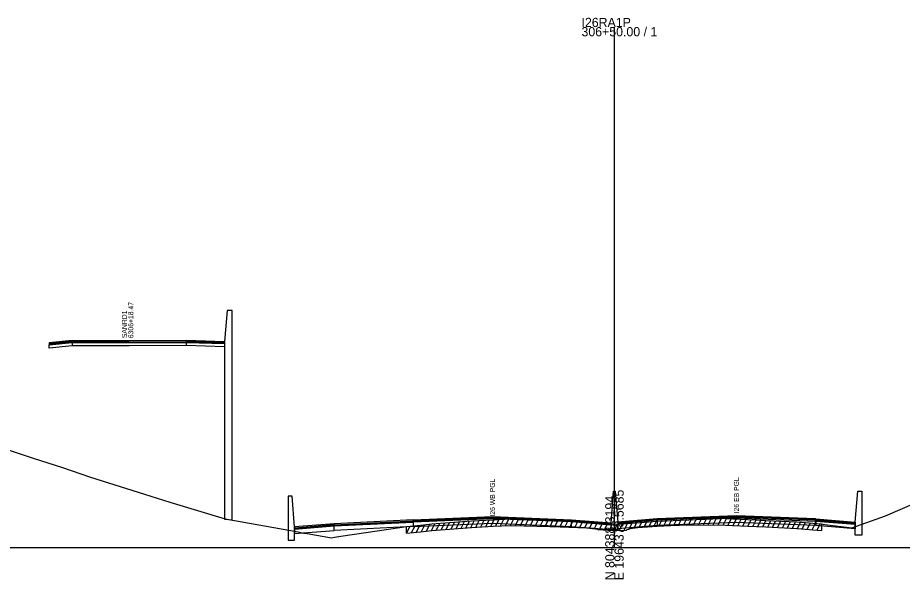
# Model space of a CAD drawing. Extents: x 1017 to 19997, y -1947 to 50737.
# Drawn here: x 12419 to 12687.3, y 6490.3 to 6660.6 of the extents above; entities that cross this region are included whole.
import ezdxf

# ---------------------------------------------------------------- set-up
doc = ezdxf.new("R2010")
doc.units = 0
for name, color, linetype in [('RD_GPK_XS_Cell', 7, 'Continuous'), ('RD_XS_Base', 7, 'Continuous'), ('RD_XS_ExGround', 7, 'Continuous'), ('RD_XS_ExPaveRet', 7, 'Continuous'), ('RD_XS_MedBWall', 7, 'Continuous'), ('RD_XS_Pave', 7, 'Continuous'), ('RD_XS_PaveOvlay', 7, 'Continuous'), ('RD_XS_TX_Notes', 7, 'Continuous')]:
    doc.layers.add(name, color=color, linetype=linetype)

msp = doc.modelspace()

# ---------------------------------------------------------------- linework, layer by layer
at = {"layer": 'RD_GPK_XS_Cell'}
for p, q in [((12600, 6500), (12600, 6657.75)), ((12000, 6500), (12600, 6500)), ((12600, 6500), (13200, 6500))]:
    msp.add_line(p, q, dxfattribs=at)
at = {"layer": 'RD_XS_Base'}
for points in [[(12428.6, 6561.38), (12435.53, 6562.12)], [(12428.6, 6560.38), (12428.6, 6561.38)], [(12435.53, 6561.12), (12428.6, 6560.38)], [(12435.53, 6562.12), (12452.85, 6562.12), (12470.18, 6562.15)], [(12435.53, 6562.12), (12435.53, 6561.12)], [(12470.18, 6561.15), (12452.85, 6561.12), (12435.53, 6561.12)], [(12470.18, 6562.15), (12481.73, 6561.79)], [(12470.18, 6561.15), (12470.18, 6562.15)], [(12481.73, 6560.79), (12470.18, 6561.15)], [(12481.73, 6561.79), (12481.73, 6560.79)], [(12587, 6507.69), (12563, 6508.65), (12539, 6507.68)], [(12613, 6507.95), (12637, 6508.91), (12661, 6507.95)], [(12515, 6506.48), (12503, 6505.52)], [(12515, 6506.48), (12539, 6507.68)], [(12515, 6505.14), (12515, 6506.48)], [(12539, 6506.34), (12515, 6505.14)], [(12539, 6507.68), (12539, 6506.34)], [(12539, 6506.34), (12563, 6507.31), (12587, 6506.35)], [(12587, 6506.35), (12587, 6507.69)], [(12599, 6506.75), (12587, 6507.69)], [(12587, 6506.35), (12599, 6505.41)], [(12599, 6505.41), (12599, 6506.75)], [(12601, 6507), (12613, 6507.95)], [(12601, 6505.66), (12601, 6507)], [(12613, 6506.61), (12601, 6505.66)], [(12613, 6507.95), (12613, 6506.61)], [(12661, 6506.61), (12637, 6507.57), (12613, 6506.61)], [(12661, 6507.95), (12661.05, 6507.94)], [(12661, 6506.61), (12661, 6507.95)], [(12661.05, 6506.6), (12661, 6506.61)], [(12661.05, 6507.94), (12673.05, 6506.98)], [(12661.05, 6506.6), (12661.05, 6507.94)], [(12661.05, 6507.94), (12661.05, 6506.6)], [(12673.05, 6505.64), (12661.05, 6506.6)], [(12673.05, 6506.98), (12673.05, 6505.64)], [(12503, 6505.52), (12503, 6504.18)], [(12503, 6504.18), (12515, 6505.14)]]:
    msp.add_lwpolyline(points, dxfattribs=at)
at = {"layer": 'RD_XS_ExGround'}
msp.add_lwpolyline([(12408.26, 6532.18), (12423.66, 6527.03), (12432.56, 6524.17), (12441.14, 6521.29), (12457.45, 6516.14), (12465.18, 6513.73), (12481.9, 6508.65), (12504.08, 6504.68), (12505.76, 6504.34), (12506.76, 6504.19), (12514.21, 6502.93), (12515.05, 6503.04), (12517.04, 6503.35), (12532.18, 6505.6), (12536.97, 6506.32), (12541.13, 6506.72), (12544.64, 6507.09), (12550.02, 6507.51), (12556.67, 6508.02), (12563.18, 6508.37), (12568.58, 6508.66), (12580.45, 6508.33), (12580.79, 6508.32), (12591.49, 6507.89), (12594.24, 6507.65), (12594.71, 6507.61), (12595.08, 6507.45), (12598.01, 6507.18), (12600, 6507.1), (12600.71, 6507.07), (12603.64, 6507.25), (12603.9, 6507.43), (12604.4, 6507.48), (12604.67, 6507.68), (12607.08, 6508.01), (12612.99, 6508.38), (12619.12, 6508.76), (12619.75, 6508.77), (12631.32, 6508.84), (12640.5, 6508.42), (12643.1, 6508.31), (12645.92, 6508.18), (12655.27, 6507.75), (12656.77, 6507.62), (12660.12, 6507.34), (12662.8, 6507.14), (12663.85, 6506.96), (12672.04, 6505.92), (12682.25, 6509.52), (12691.05, 6513.37)], dxfattribs=at)
at = {"layer": 'RD_XS_ExPaveRet'}
for p, q in [((12566.97, 6506.57), (12567.99, 6508.63)), ((12568.47, 6506.65), (12569.46, 6508.63)), ((12616.47, 6506.6), (12617.5, 6508.66)), ((12617.97, 6506.69), (12619, 6508.76)), ((12619.47, 6506.76), (12620.47, 6508.77)), ((12620.97, 6506.77), (12621.97, 6508.78)), ((12622.47, 6506.78), (12623.47, 6508.79)), ((12623.97, 6506.79), (12624.97, 6508.8)), ((12625.47, 6506.8), (12626.47, 6508.81)), ((12626.97, 6506.81), (12627.97, 6508.81)), ((12628.47, 6506.82), (12629.47, 6508.82)), ((12629.97, 6506.83), (12630.97, 6508.83)), ((12631.47, 6506.83), (12632.44, 6508.78)), ((12632.97, 6506.76), (12633.94, 6508.72)), ((12634.47, 6506.69), (12635.44, 6508.65)), ((12536.97, 6504.32), (12538.02, 6506.42)), ((12536.97, 6504.32), (12536.97, 6506.32)), ((12538.47, 6504.47), (12539.52, 6506.57)), ((12539.97, 6504.61), (12541.02, 6506.71)), ((12541.47, 6504.76), (12542.52, 6506.87)), ((12542.97, 6504.91), (12544.02, 6507.02)), ((12544.47, 6505.07), (12545.51, 6507.16)), ((12545.97, 6505.19), (12547.01, 6507.27)), ((12547.47, 6505.31), (12548.51, 6507.39)), ((12548.97, 6505.43), (12550.01, 6507.51)), ((12550.02, 6505.51), (12556.67, 6506.02)), ((12550.47, 6505.54), (12551.51, 6507.62)), ((12551.97, 6505.66), (12553.01, 6507.74)), ((12553.47, 6505.77), (12554.51, 6507.85)), ((12554.97, 6505.89), (12556.01, 6507.97)), ((12556.47, 6506), (12557.5, 6508.06)), ((12556.67, 6506.02), (12563.18, 6506.37)), ((12557.97, 6506.09), (12558.99, 6508.14)), ((12559.47, 6506.17), (12560.49, 6508.22)), ((12560.97, 6506.25), (12561.99, 6508.3)), ((12562.47, 6506.33), (12563.49, 6508.39)), ((12563.18, 6506.37), (12568.58, 6506.66)), ((12563.97, 6506.41), (12564.99, 6508.47)), ((12565.47, 6506.49), (12566.49, 6508.55)), ((12568.58, 6506.66), (12580.45, 6506.33)), ((12569.97, 6506.62), (12570.95, 6508.59)), ((12571.47, 6506.58), (12572.45, 6508.55)), ((12572.97, 6506.54), (12573.95, 6508.51)), ((12574.47, 6506.5), (12575.45, 6508.47)), ((12575.97, 6506.45), (12576.95, 6508.43)), ((12577.47, 6506.41), (12578.45, 6508.39)), ((12578.97, 6506.37), (12579.95, 6508.35)), ((12580.45, 6506.33), (12580.79, 6506.32)), ((12580.47, 6506.33), (12581.45, 6508.29)), ((12580.79, 6506.32), (12591.49, 6505.89)), ((12581.97, 6506.27), (12582.95, 6508.23)), ((12583.47, 6506.21), (12584.45, 6508.17)), ((12584.97, 6506.15), (12585.95, 6508.11)), ((12586.47, 6506.09), (12587.45, 6508.05)), ((12587.97, 6506.03), (12588.95, 6507.99)), ((12589.47, 6505.97), (12590.45, 6507.93)), ((12590.97, 6505.91), (12591.94, 6507.85)), ((12592.47, 6505.81), (12593.42, 6507.72)), ((12593.97, 6505.68), (12594.89, 6507.53)), ((12595.47, 6505.42), (12596.42, 6507.33)), ((12596.97, 6505.28), (12597.92, 6507.19)), ((12598.47, 6505.16), (12599.45, 6507.12)), ((12599.97, 6505.1), (12600.96, 6507.09)), ((12601.47, 6505.12), (12602.5, 6507.18)), ((12602.97, 6505.21), (12604.09, 6507.45)), ((12604.47, 6505.53), (12605.61, 6507.81)), ((12604.67, 6505.68), (12607.08, 6506.01)), ((12605.97, 6505.86), (12607.04, 6508)), ((12607.08, 6506.01), (12612.99, 6506.38)), ((12607.47, 6506.03), (12608.5, 6508.1)), ((12608.97, 6506.13), (12610, 6508.19)), ((12610.47, 6506.22), (12611.5, 6508.29)), ((12611.97, 6506.31), (12613, 6508.38)), ((12612.99, 6506.38), (12619.12, 6506.76)), ((12613.47, 6506.41), (12614.5, 6508.47)), ((12614.97, 6506.5), (12616, 6508.57)), ((12619.12, 6506.76), (12619.75, 6506.77)), ((12619.75, 6506.77), (12631.32, 6506.84)), ((12631.32, 6506.84), (12640.5, 6506.42)), ((12635.97, 6506.63), (12636.94, 6508.58)), ((12637.47, 6506.56), (12638.44, 6508.51)), ((12638.97, 6506.49), (12639.94, 6508.45)), ((12640.47, 6506.42), (12641.45, 6508.38)), ((12640.5, 6506.42), (12643.1, 6506.31)), ((12641.97, 6506.36), (12642.95, 6508.32)), ((12643.1, 6506.31), (12645.92, 6506.18)), ((12643.47, 6506.29), (12644.44, 6508.25)), ((12644.97, 6506.22), (12645.94, 6508.18)), ((12645.92, 6506.18), (12655.27, 6505.75)), ((12646.47, 6506.15), (12647.44, 6508.11)), ((12647.97, 6506.08), (12648.94, 6508.04)), ((12649.47, 6506.01), (12650.44, 6507.97)), ((12650.97, 6505.94), (12651.94, 6507.9)), ((12652.47, 6505.88), (12653.44, 6507.83)), ((12653.97, 6505.81), (12654.94, 6507.76)), ((12655.47, 6505.73), (12656.43, 6507.65)), ((12656.97, 6505.6), (12657.93, 6507.52)), ((12658.47, 6505.48), (12659.43, 6507.4)), ((12659.97, 6505.35), (12660.93, 6507.28)), ((12661.47, 6505.24), (12662.43, 6507.17)), ((12662.8, 6507.14), (12662.8, 6505.14)), ((12536.97, 6504.32), (12541.13, 6504.72)), ((12541.13, 6504.72), (12544.64, 6505.09)), ((12544.64, 6505.09), (12550.02, 6505.51)), ((12591.49, 6505.89), (12594.24, 6505.65)), ((12594.24, 6505.65), (12594.71, 6505.61)), ((12594.71, 6505.61), (12595.08, 6505.45)), ((12595.08, 6505.45), (12598.01, 6505.18)), ((12598.01, 6505.18), (12600, 6505.1)), ((12600, 6505.1), (12600.71, 6505.07)), ((12600.71, 6505.07), (12603.64, 6505.25)), ((12603.64, 6505.25), (12603.9, 6505.43)), ((12603.9, 6505.43), (12604.4, 6505.48)), ((12604.4, 6505.48), (12604.67, 6505.68)), ((12655.27, 6505.75), (12656.77, 6505.62)), ((12656.77, 6505.62), (12660.12, 6505.34)), ((12660.12, 6505.34), (12662.8, 6505.14))]:
    msp.add_line(p, q, dxfattribs=at)
at = {"layer": 'RD_XS_MedBWall'}
for points in [[(12484.04, 6571.85), (12482.59, 6571.8), (12481.73, 6562.42)], [(12484.04, 6508.38), (12484.04, 6571.85)], [(12481.73, 6562.42), (12481.73, 6508.55)], [(12599, 6507.4), (12599.75, 6517), (12600.25, 6517), (12601, 6507.66)], [(12673.05, 6507.66), (12673.8, 6517), (12675.05, 6517)], [(12675.05, 6517), (12675.05, 6503.66)], [(12503, 6506.2), (12502.25, 6515.54), (12501, 6515.54)], [(12501, 6515.54), (12501, 6502.2)], [(12481.73, 6508.55), (12484.04, 6508.38)], [(12503, 6502.2), (12503, 6506.2)], [(12599, 6505.4), (12599, 6507.4)], [(12601, 6507.66), (12601, 6505.4)], [(12673.05, 6503.66), (12673.05, 6507.66)], [(12601, 6505.4), (12599, 6505.4)], [(12675.05, 6503.66), (12673.05, 6503.66)], [(12501, 6502.2), (12503, 6502.2)]]:
    msp.add_lwpolyline(points, dxfattribs=at)
at = {"layer": 'RD_XS_Pave'}
for points in [[(12435.53, 6562.43), (12428.6, 6561.72)], [(12470.18, 6562.47), (12452.85, 6562.44), (12435.53, 6562.43)], [(12435.53, 6562.43), (12435.53, 6562.12)], [(12470.18, 6562.15), (12470.18, 6562.47)], [(12470.18, 6562.47), (12481.73, 6562.11)], [(12428.6, 6561.38), (12435.53, 6562.12)], [(12428.6, 6561.72), (12428.6, 6561.38)], [(12435.53, 6562.12), (12452.85, 6562.12), (12470.18, 6562.15)], [(12481.73, 6561.79), (12470.18, 6562.15)], [(12481.73, 6562.11), (12481.73, 6561.79)], [(12539, 6508.02), (12563, 6508.99), (12587, 6508.03)], [(12587, 6507.69), (12563, 6508.65), (12539, 6507.68)], [(12661, 6508.29), (12637, 6509.25), (12613, 6508.29)], [(12613, 6507.95), (12637, 6508.91), (12661, 6507.95)], [(12515, 6506.82), (12503, 6505.86)], [(12503, 6505.52), (12515, 6506.48)], [(12515, 6506.82), (12539, 6508.02)], [(12539, 6507.68), (12515, 6506.48)], [(12515, 6506.48), (12515, 6506.82)], [(12539, 6507.68), (12539, 6508.02)], [(12587, 6508.03), (12599, 6507.09)], [(12587, 6507.69), (12587, 6508.03)], [(12599, 6506.75), (12587, 6507.69)], [(12599, 6507.09), (12599, 6506.75)], [(12613, 6508.29), (12601, 6507.34)], [(12601, 6507), (12613, 6507.95)], [(12601, 6507.34), (12601, 6507)], [(12613, 6508.29), (12613, 6507.95)], [(12661, 6508.29), (12661.05, 6508.28)], [(12661, 6507.95), (12661, 6508.29)], [(12661.05, 6507.94), (12661, 6507.95)], [(12661.05, 6508.28), (12673.05, 6507.32)], [(12661.05, 6507.94), (12661.05, 6508.28)], [(12661.05, 6508.28), (12661.05, 6507.94)], [(12673.05, 6506.98), (12661.05, 6507.94)], [(12673.05, 6507.32), (12673.05, 6506.98)], [(12503, 6505.86), (12503, 6505.52)]]:
    msp.add_lwpolyline(points, dxfattribs=at)
at = {"layer": 'RD_XS_PaveOvlay'}
for points in [[(12435.53, 6562.75), (12428.6, 6562.04)], [(12428.6, 6561.72), (12435.53, 6562.43)], [(12435.53, 6562.75), (12452.85, 6562.75), (12470.18, 6562.79)], [(12435.53, 6562.43), (12435.53, 6562.75)], [(12470.18, 6562.47), (12452.85, 6562.44), (12435.53, 6562.43)], [(12470.18, 6562.79), (12470.18, 6562.47)], [(12470.18, 6562.79), (12481.73, 6562.42)], [(12481.73, 6562.11), (12470.18, 6562.47)], [(12481.73, 6562.42), (12481.73, 6562.11)], [(12428.6, 6562.04), (12428.6, 6561.72)], [(12539, 6508.36), (12563, 6509.32), (12587, 6508.36)], [(12587, 6508.03), (12563, 6508.99), (12539, 6508.02)], [(12613, 6508.62), (12601, 6507.66)], [(12661, 6508.62), (12637, 6509.58), (12613, 6508.62)], [(12613, 6508.29), (12637, 6509.25), (12661, 6508.29)], [(12613, 6508.62), (12613, 6508.29)], [(12661, 6508.29), (12661, 6508.62)], [(12661, 6508.62), (12661.05, 6508.62)], [(12661.05, 6508.62), (12673.05, 6507.66)], [(12661.05, 6508.28), (12661.05, 6508.62)], [(12661.05, 6508.62), (12661.05, 6508.28)], [(12515, 6507.16), (12503, 6506.2)], [(12503, 6505.86), (12515, 6506.82)], [(12503, 6506.2), (12503, 6505.86)], [(12539, 6508.36), (12515, 6507.16)], [(12515, 6506.82), (12539, 6508.02)], [(12515, 6506.82), (12515, 6507.16)], [(12539, 6508.02), (12539, 6508.36)], [(12587, 6508.36), (12599, 6507.4)], [(12587, 6508.03), (12587, 6508.36)], [(12599, 6507.09), (12587, 6508.03)], [(12599, 6507.4), (12599, 6507.09)], [(12601, 6507.34), (12613, 6508.29)], [(12601, 6507.66), (12601, 6507.34)], [(12661.05, 6508.28), (12661, 6508.29)], [(12673.05, 6507.32), (12661.05, 6508.28)], [(12673.05, 6507.66), (12673.05, 6507.32)]]:
    msp.add_lwpolyline(points, dxfattribs=at)

# ---------------------------------------------------------------- texts
at = {"layer": 'RD_GPK_XS_Cell'}
for s, p in [('I26RA1P', (12590, 6657.75)), ('306+50.00 / 1', (12590, 6654.95))]:
    msp.add_text(s, height=2.8, dxfattribs=at).set_placement(p)
for s, p in [('E 1964378.5685', (12602.8, 6490)), ('N 804388.3194', (12600, 6490))]:
    msp.add_text(s, height=2.8, rotation=90, dxfattribs=at).set_placement(p)
at = {"layer": 'RD_XS_TX_Notes'}
for s, p in [(' 6306+18.47', (12454.08, 6562.83)), (' SANRD1', (12452.13, 6562.83)), ('I26 WB PGL', (12563.75, 6509.32)), ('I26 EB PGL', (12637.75, 6510.31))]:
    msp.add_text(s, height=1.5, rotation=90, dxfattribs=at).set_placement(p)

doc.saveas('drawing.dxf')
